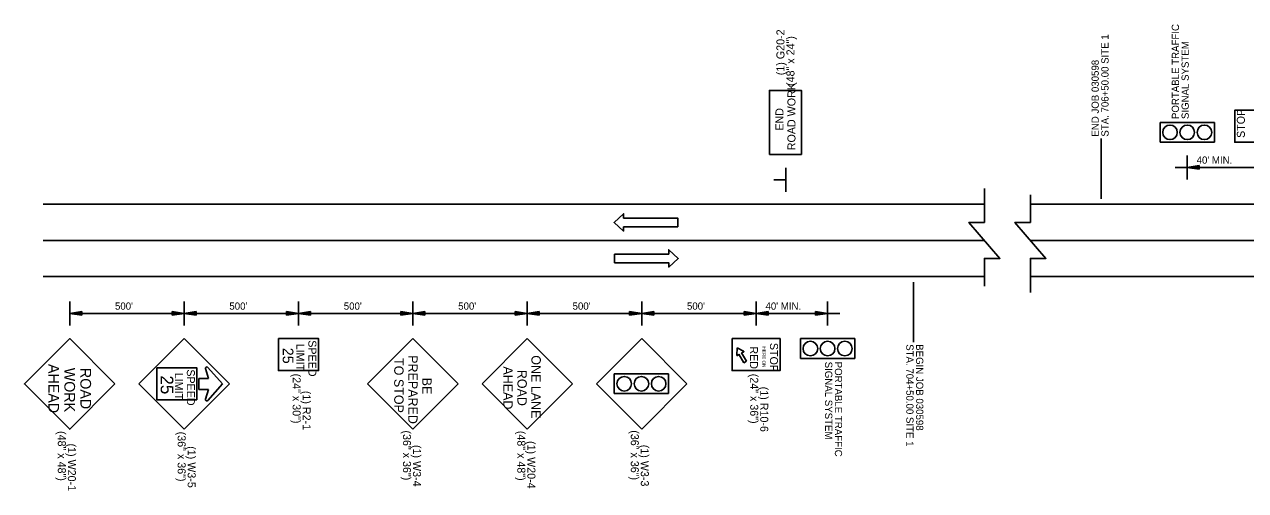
# Model space of a CAD drawing. Extents: x 1368648 to 1927880, y -1037443 to 380209.
# Drawn here: x 1369330 to 1370245, y 377702 to 378051 of the extents above; entities that cross this region are included whole.
import ezdxf

# ---------------------------------------------------------------- set-up
doc = ezdxf.new("R2010")
doc.units = 0
for name, color, linetype in [('Default', 7, 'Continuous'), ('Dimensions', 7, 'Continuous'), ('R_Draft', 7, 'Continuous'), ('R_Signs', 7, 'Continuous'), ('R_Signs_Annot', 7, 'Continuous')]:
    doc.layers.add(name, color=color, linetype=linetype)

# ---------------------------------------------------------------- blocks, each defined once
blk = doc.blocks.new('ARROW')
at = {"layer": 'R_Draft'}
for p, q in [((-2, 0.3), (0, 0)), ((-2, 0.3), (-2, -0.3)), ((-2, 0.25), (-0.334, 0)), ((-2, 0.199), (-0.678, 0)), ((-2, 0.149), (-1.011, 0)), ((-2, 0.097), (-1.35, 0)), ((-2, 0.047), (-1.684, 0)), ((-2, -0.3), (0, 0)), ((-2, -0.098), (-1.35, 0)), ((-2, -0.199), (-0.678, 0)), ((-2, -0.25), (-0.334, 0)), ((-2, -0.149), (-1.011, 0)), ((-2, -0.047), (-1.684, 0))]:
    blk.add_line(p, q, dxfattribs=at)

msp = doc.modelspace()

# ---------------------------------------------------------------- linework, layer by layer
at = {"layer": 'Default'}
for p, q in [((1370137.06, 377920.6), (1370137.06, 377965.73)), ((1370201.54, 377953.17), (1370201.54, 377935.12)), ((1369900.8, 377925.91), (1369900.8, 377943.96)), ((1370201.54, 377944.15), (1370192.51, 377944.15)), ((1370255.15, 377944.15), (1370201.54, 377944.15)), ((1369900.8, 377934.93), (1369891.78, 377934.93)), ((1369344.15, 377916.51), (1370049.53, 377916.51)), ((1370509.44, 377916.51), (1370084.03, 377916.51)), ((1369344.15, 377889.43), (1370049.52, 377889.43)), ((1370509.44, 377889.43), (1370084.04, 377889.43)), ((1369344.15, 377862.36), (1370049.53, 377862.36)), ((1370509.44, 377862.36), (1370084.03, 377862.36)), ((1369996.5, 377858.26), (1369996.5, 377813.14)), ((1369363.98, 377825.69), (1369363.98, 377843.74)), ((1369449.72, 377825.69), (1369449.72, 377843.74)), ((1369449.72, 377825.69), (1369449.72, 377843.74)), ((1369535.46, 377825.69), (1369535.46, 377843.74)), ((1369535.46, 377825.69), (1369535.46, 377843.74)), ((1369621.2, 377825.69), (1369621.2, 377843.74)), ((1369621.2, 377825.69), (1369621.2, 377843.74)), ((1369706.93, 377825.69), (1369706.93, 377843.74)), ((1369792.67, 377825.69), (1369792.67, 377843.74)), ((1369878.41, 377825.69), (1369878.41, 377843.74)), ((1369932.02, 377825.69), (1369932.02, 377843.74)), ((1369363.98, 377834.72), (1369449.72, 377834.72)), ((1369363.98, 377834.72), (1369373.01, 377834.72)), ((1369449.72, 377834.72), (1369535.46, 377834.72)), ((1369449.72, 377834.72), (1369458.75, 377834.72)), ((1369449.72, 377834.72), (1369458.75, 377834.72)), ((1369535.46, 377834.72), (1369544.48, 377834.72)), ((1369535.46, 377834.72), (1369621.2, 377834.72)), ((1369535.46, 377834.72), (1369544.48, 377834.72)), ((1369621.2, 377834.72), (1369630.22, 377834.72)), ((1369621.2, 377834.72), (1369706.93, 377834.72)), ((1369621.2, 377834.72), (1369630.22, 377834.72)), ((1369706.93, 377834.72), (1369792.67, 377834.72)), ((1369706.93, 377834.72), (1369715.96, 377834.72)), ((1369792.67, 377834.72), (1369878.41, 377834.72)), ((1369792.67, 377834.72), (1369801.7, 377834.72)), ((1369878.41, 377834.72), (1369887.43, 377834.72)), ((1369878.41, 377834.72), (1369932.02, 377834.72)), ((1369932.02, 377834.72), (1369941.05, 377834.72))]:
    msp.add_line(p, q, dxfattribs=at)
for points in [[(1370049.53, 377928.37), (1370049.53, 377902.97), (1370037.94, 377902.97), (1370061.11, 377875.89), (1370049.53, 377875.89), (1370049.53, 377855.23)], [(1370084.03, 377850.49), (1370084.03, 377875.89), (1370095.62, 377875.89), (1370072.45, 377902.97), (1370084.03, 377902.97), (1370084.03, 377923.63)]]:
    msp.add_lwpolyline(points, dxfattribs=at)
at = {"layer": 'Dimensions'}
for p, q in [((1369819.7, 377899.72), (1369779.13, 377899.72)), ((1369772.38, 377879.14), (1369812.96, 377879.14))]:
    msp.add_line(p, q, dxfattribs=at)
for points in [[(1369819.7, 377899.72), (1369819.7, 377906.22), (1369779.13, 377906.22), (1369779.13, 377909.47), (1369772, 377902.97), (1369779.13, 377896.47), (1369779.13, 377899.72)], [(1369772.38, 377879.14), (1369772.38, 377872.65), (1369812.96, 377872.65), (1369812.96, 377869.4), (1369820.08, 377875.89), (1369812.96, 377882.39), (1369812.96, 377879.14)]]:
    msp.add_lwpolyline(points, dxfattribs=at)
at = {"layer": 'R_Signs'}
for p, q in [((1370181.22, 377963.05), (1370181.22, 377977.86)), ((1370181.22, 377977.86), (1370221.86, 377977.86)), ((1370221.86, 377977.86), (1370221.86, 377963.05)), ((1370221.86, 377963.05), (1370181.22, 377963.05)), ((1369449.72, 377815.81), (1369415.78, 377781.87)), ((1369483.66, 377781.87), (1369449.72, 377815.81)), ((1369621.2, 377815.81), (1369587.25, 377781.87)), ((1369655.14, 377781.87), (1369621.2, 377815.81)), ((1369706.93, 377815.81), (1369672.99, 377781.87)), ((1369740.87, 377781.87), (1369706.93, 377815.81)), ((1369792.67, 377815.81), (1369758.73, 377781.87)), ((1369826.61, 377781.87), (1369792.67, 377815.81)), ((1369911.7, 377801.01), (1369911.7, 377815.81)), ((1369911.7, 377815.81), (1369952.34, 377815.81)), ((1369952.34, 377815.81), (1369952.34, 377801.01)), ((1369864.19, 377808.82), (1369863.95, 377803.49)), ((1369868.93, 377806.36), (1369864.19, 377808.82)), ((1369868.93, 377806.36), (1369868.93, 377806.36)), ((1369863.95, 377803.49), (1369863.95, 377803.49)), ((1369864.66, 377803.19), (1369865.6, 377804.2)), ((1369864.66, 377803.19), (1369864.66, 377803.19)), ((1369865.6, 377804.2), (1369869.34, 377797.73)), ((1369867.49, 377805.29), (1369868.83, 377805.6)), ((1369871.23, 377798.82), (1369867.49, 377805.29)), ((1369868.83, 377805.6), (1369868.83, 377805.6)), ((1369869.34, 377797.73), (1369871.23, 377798.82)), ((1369952.34, 377801.01), (1369911.7, 377801.01)), ((1369465.82, 377793.4), (1369467.88, 377785.9)), ((1369478.48, 377781.87), (1369467.46, 377794.29)), ((1369772.16, 377774.58), (1369772.16, 377789.39)), ((1369772.16, 377789.39), (1369812.8, 377789.39)), ((1369812.8, 377789.39), (1369812.8, 377774.58)), ((1369415.78, 377781.87), (1369449.72, 377747.93)), ((1369449.72, 377747.93), (1369483.66, 377781.87)), ((1369460.81, 377785.9), (1369460.81, 377777.79)), ((1369467.88, 377785.9), (1369460.81, 377785.9)), ((1369467.48, 377769.48), (1369478.48, 377781.87)), ((1369587.25, 377781.87), (1369621.2, 377747.95)), ((1369621.2, 377747.95), (1369655.14, 377781.87)), ((1369672.99, 377781.87), (1369706.93, 377747.95)), ((1369706.93, 377747.95), (1369740.87, 377781.87)), ((1369758.73, 377781.87), (1369792.67, 377747.93)), ((1369792.67, 377747.93), (1369826.61, 377781.87)), ((1369460.81, 377777.79), (1369467.88, 377777.79)), ((1369467.88, 377777.79), (1369465.84, 377770.37)), ((1369812.8, 377774.58), (1369772.16, 377774.58))]:
    msp.add_line(p, q, dxfattribs=at)
for points in [[(1369888.41, 377953.89), (1369888.41, 378001.89), (1369912.41, 378001.89), (1369912.41, 377953.89)], [(1370273.15, 377963.05), (1370273.15, 377987.05), (1370237.15, 377987.05), (1370237.15, 377963.05)], [(1369397.92, 377781.87), (1369363.98, 377815.81), (1369330.04, 377781.87), (1369363.98, 377747.93)], [(1369520.46, 377815.81), (1369520.46, 377791.81), (1369550.46, 377791.81), (1369550.46, 377815.81)], [(1369860.41, 377815.81), (1369860.41, 377791.81), (1369896.41, 377791.81), (1369896.41, 377815.81)], [(1369429.2, 377794.03), (1369429.2, 377770.01), (1369459.23, 377770.01), (1369459.23, 377794.03)]]:
    msp.add_lwpolyline(points, close=True, dxfattribs=at)
for centre in [(1370188.64, 377970.45), (1370201.54, 377970.45), (1370201.55, 377970.45), (1370214.45, 377970.45), (1369919.11, 377808.41), (1369932.01, 377808.41), (1369932.01, 377808.41), (1369944.92, 377808.41), (1369779.57, 377781.99), (1369792.48, 377781.99), (1369792.48, 377781.99), (1369805.38, 377781.99)]:
    msp.add_circle(centre, 5.48, dxfattribs=at)
for centre, radius, start, end in [((1369868.74, 377806), 0.41, 283.0563, 62.59672), ((1369864.36, 377803.47), 0.41, 177.40326, 316.94368), ((1369466.74, 377793.65), 0.961, 41.58619, 195.37776), ((1369466.76, 377770.12), 0.961, 164.62224, 318.41381)]:
    msp.add_arc(centre, radius, start, end, dxfattribs=at)

# ---------------------------------------------------------------- block references
at = {"layer": 'Default', "xscale": 4.512500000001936, "yscale": 4.512499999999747, "rotation": 180}
for p in [(1370201.54, 377944.15), (1369363.98, 377834.72), (1369449.72, 377834.72), (1369535.46, 377834.72), (1369621.2, 377834.72), (1369706.93, 377834.72), (1369706.93, 377834.72), (1369792.67, 377834.72), (1369792.67, 377834.72), (1369878.41, 377834.72)]:
    msp.add_blockref('ARROW', p, dxfattribs=at)
at = {"layer": 'Default', "xscale": 4.512500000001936, "yscale": 4.512499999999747}
for p in [(1369449.72, 377834.72), (1369535.46, 377834.72), (1369621.2, 377834.72), (1369706.93, 377834.72), (1369792.67, 377834.72), (1369792.67, 377834.72), (1369878.41, 377834.72), (1369878.41, 377834.72), (1369932.02, 377834.72)]:
    msp.add_blockref('ARROW', p, dxfattribs=at)

# ---------------------------------------------------------------- texts
at = {"layer": 'Default'}
for s, rotation, p in [('PORTABLE TRAFFIC ', 90, (1370195.35, 377980.41)), ('STA. 706+50.00 SITE 1', 90, (1370142.58, 377967.23)), ('SIGNAL SYSTEM', 90, (1370202.69, 377980.41)), ('END JOB 030598', 90, (1370135.25, 377967.23)), ("40' MIN.", 360, (1370208.58, 377946.95)), ('STA. 704+50.00 SITE 1', 270, (1369990.98, 377811.64)), ('BEGIN JOB 030598', 270, (1369998.31, 377811.64)), ('SIGNAL SYSTEM', 270, (1369930.12, 377798.55)), ('PORTABLE TRAFFIC ', 270, (1369937.45, 377798.55))]:
    msp.add_text(s, height=5.415, rotation=rotation, dxfattribs=at).set_placement(p)
for s, p in [("500'", (1369397.92, 377837.52)), ("500'", (1369483.65, 377837.52)), ("500'", (1369569.39, 377837.52)), ("500'", (1369655.13, 377837.52)), ("500'", (1369740.87, 377837.52)), ("500'", (1369826.6, 377837.52)), ("40' MIN.", (1369885.45, 377837.52))]:
    msp.add_text(s, height=5.415, dxfattribs=at).set_placement(p)
at = {"layer": 'R_Signs'}
for s, height, rotation, p in [('ROAD WORK', 6, 90, (1369907.91, 377957.03)), ('END', 6, 90, (1369898.91, 377971.73)), ('STOP', 6, 90, (1370244.74, 377966.24)), ('25', 8, 270, (1369523.64, 377808.94)), ('LIMIT', 6, 270, (1369533.86, 377812.04)), ('SPEED', 6, 270, (1369542.86, 377814.6)), ('RED', 6, 270, (1369873.81, 377809.99)), ('HERE ON', 2.5, 270, (1369883.06, 377809.96)), ('STOP', 6, 270, (1369888.81, 377812.63)), ('AHEAD', 8, 270, (1369347.98, 377796.83)), ('TO STOP', 7, 270, (1369607.2, 377801.23)), ('PREPARED', 7, 270, (1369617.7, 377803.4)), ('ONE LANE', 7, 270, (1369710.05, 377803.33)), ('WORK', 8, 270, (1369359.98, 377793.99)), ('ROAD', 8, 270, (1369371.98, 377793.85)), ('25', 9.5, 270, (1369432.16, 377788.24)), ('LIMIT', 6, 270, (1369442.78, 377790.24)), ('SPEED', 6, 270, (1369451.78, 377792.8)), ('AHEAD', 7, 270, (1369689.05, 377794.99)), ('ROAD', 7, 270, (1369699.55, 377792.44)), ('BE', 7, 270, (1369628.2, 377786.56))]:
    msp.add_text(s, height=height, rotation=rotation, dxfattribs=at).set_placement(p)
at = {"layer": 'R_Signs_Annot'}
for s, rotation, p in [('(1) G20-2', 90, (1369899.65, 378013.26)), ('(48" x 24")', 90, (1369907.17, 378005.23)), ('(24" x 30")', 270, (1369531.07, 377789.58)), ('(24" x 36")', 270, (1369874.02, 377789.49)), ('(1) R10-6', 270, (1369881.53, 377779.78)), ('(1) R2-1', 270, (1369538.58, 377776.68)), ('(48" x 48")', 270, (1369355.08, 377746.55)), ('(36" x 36")', 270, (1369444.9, 377746.07)), ('(36" x 36")', 270, (1369613.75, 377746.99)), ('(48" x 48")', 270, (1369699.49, 377746.71)), ('(36" x 36")', 270, (1369784.51, 377747.13)), ('(1) W20-1', 270, (1369362.59, 377737.2)), ('(1) W3-5', 270, (1369452.41, 377735.21)), ('(1) W3-4', 270, (1369621.27, 377736.13)), ('(1) W20-4', 270, (1369707, 377739.06)), ('(1) W3-3', 270, (1369792.02, 377736.26))]:
    msp.add_text(s, height=6, rotation=rotation, dxfattribs=at).set_placement(p)

doc.saveas('drawing.dxf')
